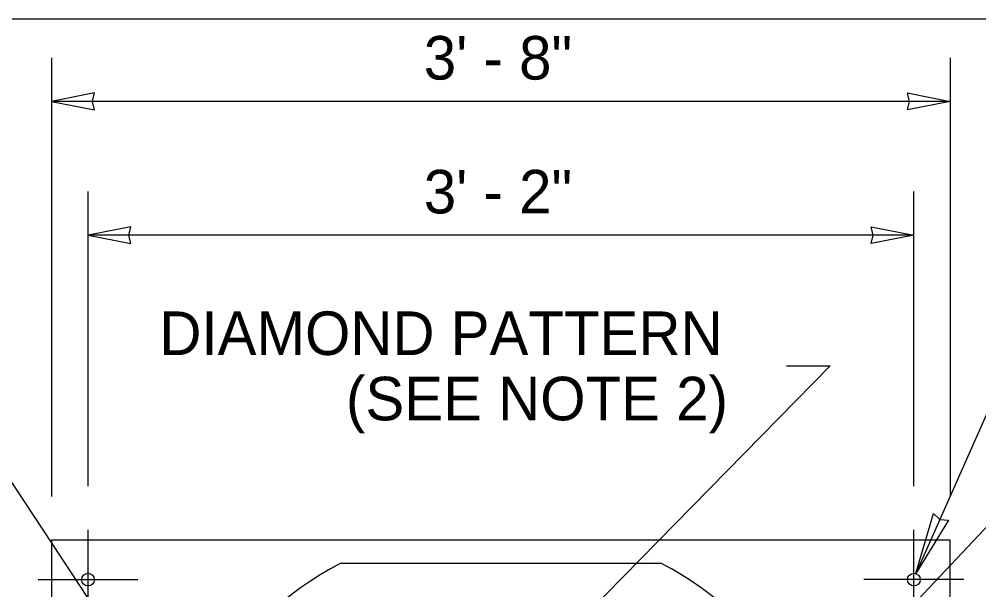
# Model space of a CAD drawing. Extents: x 99862 to 103151, y 100000 to 105076.
# Drawn here: x 100202.6 to 100555, y 101865.9 to 102075.5 of the extents above; entities that cross this region are included whole.
import ezdxf

# ---------------------------------------------------------------- set-up
doc = ezdxf.new("R2010")
doc.units = 0
for name, color, linetype in [('Level 1', 7, 'Continuous'), ('Level 10', 7, 'Continuous'), ('Level 11', 7, 'Continuous'), ('Level 15', 7, 'Continuous'), ('Level 20', 7, 'Continuous')]:
    doc.layers.add(name, color=color, linetype=linetype)

msp = doc.modelspace()

# ---------------------------------------------------------------- linework, layer by layer
at = {"layer": 'Level 1'}
msp.add_lwpolyline([(99862, 99999.5), (103151, 99999.5), (103151, 102075.5), (99862, 102075.5)], close=True, dxfattribs=at)
at = {"layer": 'Level 10'}
for p, q in [((100214.54, 101884.15), (100214.54, 101644.15)), ((100544.54, 101884.15), (100214.54, 101884.15)), ((100544.54, 101644.15), (100544.54, 101884.15))]:
    msp.add_line(p, q, dxfattribs=at)
for centre in [(100227.9, 101869.62), (100531.18, 101869.62)]:
    msp.add_circle(centre, 2.34, dxfattribs=at)
at = {"layer": 'Level 11'}
msp.add_line((100320.78, 101875.72), (100438.31, 101875.72), dxfattribs=at)
for start, end in [(117.7782, 242.2218), (297.7782, 62.2218)]:
    msp.add_arc((100379.54, 101764.15), 126.09, start, end, dxfattribs=at)
at = {"layer": 'Level 15'}
for p, q in [((100214.54, 102061.32), (100214.54, 101900.15)), ((100544.54, 102061.32), (100544.54, 101900.15)), ((100544.54, 102045.32), (100214.54, 102045.32)), ((100227.9, 101903.97), (100227.9, 102012.15)), ((100531.18, 101903.97), (100531.18, 102012.15)), ((100595.06, 102014.17), (100531.87, 101871.86)), ((100531.18, 101996.15), (100227.9, 101996.15)), ((100500.41, 101948.14), (100381.98, 101827.43)), ((100484.41, 101948.14), (100500.41, 101948.14)), ((100291.96, 101765.83), (100175.59, 101942.26)), ((100595.06, 101928.45), (100468.36, 101794.16)), ((100227.9, 101851.28), (100227.9, 101887.97)), ((100531.18, 101851.28), (100531.18, 101887.97)), ((100209.56, 101869.62), (100246.25, 101869.62)), ((100549.53, 101869.62), (100512.84, 101869.62))]:
    msp.add_line(p, q, dxfattribs=at)
for points in [[(100214.54, 102045.32), (100230.27, 102042.24), (100229.54, 102045.32), (100230.27, 102048.41)], [(100544.54, 102045.32), (100528.82, 102042.24), (100529.55, 102045.32), (100528.82, 102048.41)], [(100227.9, 101996.15), (100243.63, 101993.07), (100242.9, 101996.15), (100243.63, 101999.24)], [(100531.18, 101996.15), (100515.46, 101993.07), (100516.19, 101996.15), (100515.46, 101999.24)], [(100531.87, 101871.86), (100538.4, 101893.94), (100540.7, 101891.76), (100543.86, 101891.52)]]:
    msp.add_lwpolyline(points, close=True, dxfattribs=at)

# ---------------------------------------------------------------- texts
at = {"layer": 'Level 20'}
for s, p in [('3\' - 8"', (100351.21, 102053.32)), ('3\' - 2"', (100351.21, 102004.15)), ('DIAMOND PATTERN', (100254.11, 101952.14)), ('(SEE NOTE 2)', (100322.64, 101928.14))]:
    msp.add_text(s, height=16, dxfattribs=at).set_placement(p)

doc.saveas('drawing.dxf')
